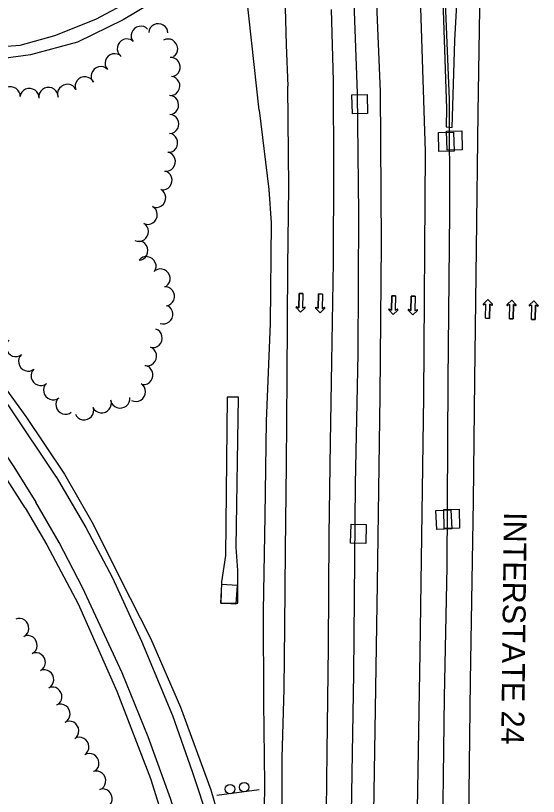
# Model space of a CAD drawing. Extents: x 1746010 to 1754829, y 655801 to 663091.
# Drawn here: x 1753745.9 to 1754020.4, y 656558.2 to 656968.4 of the extents above; entities that cross this region are included whole.
import ezdxf

# ---------------------------------------------------------------- set-up
doc = ezdxf.new("R2010")
doc.units = 0
for name, color, linetype in [('SURVEY - AERIAL SURVEY - Photo Control - Points - Elevations', 7, 'Continuous'), ('SURVEY - AERIAL SURVEY - Photo Control - Points - Locators', 7, 'Continuous'), ('SURVEY - AERIAL SURVEY - Photo Control - Points - Numbers', 7, 'Continuous'), ('SURVEY - AERIAL SURVEY - Photo Control with Text', 7, 'Continuous'), ('SURVEY - CENTERLINE - Existing Roads Text', 7, 'Continuous'), ('SURVEY - CENTERLINE - Preliminary - Development', 7, 'Continuous'), ('SURVEY - CONTROL - Points - Numbers', 7, 'Continuous'), ('SURVEY - DRAINAGE - Area Shapes - Points - Elevations', 7, 'Continuous')]:
    doc.layers.add(name, color=color, linetype=linetype)

msp = doc.modelspace()

# ---------------------------------------------------------------- linework, layer by layer
at = {"layer": 'SURVEY - AERIAL SURVEY - Photo Control - Points - Elevations'}
msp.add_lwpolyline([(1753857, 656767.99), (1753856.02, 656684.7), (1753853.97, 656670.89), (1753853.69, 656659.8), (1753862.61, 656659.78), (1753862.57, 656676.91), (1753861.67, 656689.16), (1753862.86, 656768.04), (1753857, 656767.99)], dxfattribs=at)
at = {"layer": 'SURVEY - AERIAL SURVEY - Photo Control - Points - Locators'}
for points in [[(1753750.9, 656709.87), (1753724.61, 656750.6), (1753704.23, 656778), (1753683.06, 656805.93), (1753655.94, 656838.53), (1753609.06, 656894.35), (1753560.09, 656951.56), (1753528.4, 656989.82), (1753505.99, 657020.44), (1753481.56, 657055.42), (1753460.95, 657096.18), (1753444.01, 657134.51), (1753427.57, 657178.16), (1753416.96, 657225.51), (1753408.73, 657266.76), (1753402.63, 657320.94), (1753400.61, 657379.59), (1753400.54, 657432.05), (1753399.41, 657468.62), (1753398.28, 657476.21)], [(1753403.75, 657476.1), (1753404.01, 657474.57), (1753405.2, 657457.5), (1753406.48, 657401.1), (1753409.51, 657341.24), (1753411.13, 657298.98), (1753413.05, 657276.64), (1753417.91, 657251.78), (1753427.36, 657204.55), (1753437.72, 657170.32), (1753449.26, 657138.75), (1753473.91, 657083.79), (1753493.41, 657050.04), (1753514.93, 657018.21), (1753543.67, 656981.05), (1753569.98, 656950.08), (1753593.84, 656921.5), (1753635.62, 656871.89), (1753673.8, 656825.81), (1753692.62, 656804.39), (1753707.43, 656785.04), (1753725.46, 656760.68), (1753744.98, 656731.33), (1753756.51, 656712.8)], [(1753767.31, 656725.98), (1753742.66, 656762.94), (1753722.84, 656789.81), (1753697.42, 656821.53), (1753664.77, 656860.89), (1753628.33, 656904.67), (1753587.35, 656953.18), (1753554.25, 656993.6), (1753530.02, 657024.53), (1753510.82, 657053.49), (1753492.62, 657084.85), (1753475.79, 657118.57), (1753459.38, 657156.41), (1753445.67, 657196.3), (1753437.31, 657229.21), (1753429.3, 657272.81), (1753425.21, 657322.07), (1753423.6, 657371.6), (1753421.91, 657422.15), (1753420.94, 657468), (1753419.62, 657475.78)], [(1753423.3, 657475.71), (1753424.3, 657466.91), (1753426.17, 657420.04), (1753427.09, 657355.71), (1753429.38, 657313.47), (1753432.96, 657276.04), (1753438.61, 657242.9), (1753446.99, 657205.31), (1753459.75, 657165.22), (1753475.12, 657126.8), (1753497.06, 657082.9), (1753524.77, 657037.47), (1753551.83, 657000.76), (1753586.14, 656960.76), (1753635.92, 656900.77), (1753699.64, 656825.91), (1753726.34, 656792.07), (1753751.29, 656757.89), (1753771.59, 656727.52)], [(1753965.29, 657045.03), (1753969.78, 656986.81), (1753972.15, 656919.55), (1753972.04, 656909.9), (1753975.16, 656909.61), (1753976.56, 656955.34), (1753980.46, 657028.6), (1753982.03, 657067.54)], [(1753991.68, 657069.51), (1753989.79, 656994.07), (1753988.51, 656917.34), (1753987.63, 656845.93), (1753986.9, 656777.13), (1753986.19, 656713.33), (1753984.5, 656618.92), (1753983.53, 656530.59), (1753982.02, 656453.23), (1753981.29, 656391.76), (1753979.87, 656290.99), (1753978.52, 656188.25), (1753977.29, 656086), (1753975.64, 655980.75), (1753974.7, 655894.53), (1753973.26, 655807.54)], [(1753945.21, 655807.54), (1753945.71, 655839.43), (1753947.46, 655954.84), (1753949.86, 656090.09), (1753951.64, 656208.18), (1753953.96, 656365.1), (1753956.15, 656510.33), (1753958.33, 656633.76), (1753960.21, 656768.19), (1753961.13, 656897.07), (1753957.75, 656999.64), (1753954.79, 657040.59)], [(1753934.34, 656999.68), (1753937.35, 656928.49), (1753937.83, 656848.86), (1753937.15, 656768.64), (1753935.67, 656669.84), (1753934.34, 656582.14), (1753932.9, 656495.46), (1753931.11, 656385.87), (1753929.83, 656290.6), (1753928.48, 656204.07), (1753926.32, 656083.91), (1753924.94, 655990.25), (1753923.13, 655865.62), (1753922.15, 655807.78)], [(1753886.83, 656992.14), (1753888.03, 656953.03), (1753888.8, 656931.26)], [(1753631.32, 656977.42), (1753657.14, 656965.74), (1753674.64, 656959.75), (1753692.93, 656955.53), (1753710.33, 656952.86), (1753731.8, 656951.72), (1753748.29, 656952.91), (1753766.54, 656957.92), (1753787.96, 656966.58), (1753807.07, 656976.95)], [(1753873.7, 656918.81), (1753867.13, 656979.71)], [(1753818.01, 656975.55), (1753802.43, 656966.23), (1753778.48, 656954.5), (1753753.72, 656947.84), (1753739.58, 656945.85), (1753716.1, 656946.27), (1753683.43, 656951.62), (1753660.09, 656959.1), (1753635.24, 656970.59)], [(1753911.58, 656971.59), (1753912.64, 656934.08), (1753912.82, 656887.25), (1753912.7, 656839.09), (1753911.76, 656786.44), (1753911.02, 656744.09), (1753910.41, 656695.47), (1753910.01, 656636.87), (1753909.36, 656581.72), (1753908.73, 656535.43), (1753907.55, 656485.64), (1753906.86, 656418.94), (1753906.17, 656369.03), (1753905.58, 656318.08), (1753904.54, 656261.45), (1753903.46, 656192.68), (1753902.26, 656132.87), (1753901.8, 656071.81), (1753900.44, 656014.99), (1753899.79, 655943.06), (1753898.72, 655891.08), (1753897.3, 655813.85), (1753897.22, 655808.04)], [(1753885.79, 656539.28), (1753885.89, 656578.58), (1753886.86, 656614.81), (1753887.19, 656647.39), (1753887.64, 656687.82), (1753888.14, 656732.45), (1753888.46, 656778.56), (1753888.91, 656836.35), (1753889.39, 656878.3), (1753888.8, 656931.26)], [(1753873.7, 656918.81), (1753878.92, 656877.06), (1753880.13, 656859.47), (1753879.47, 656806.65), (1753877.54, 656755.42), (1753876.71, 656705.59), (1753875.89, 656655.77), (1753875.99, 656607.65), (1753876.55, 656564.64), (1753875.84, 656511.45), (1753875.98, 656470.45), (1753871.82, 656470.28), (1753871.62, 656472.92)], [(1753771.59, 656727.52), (1753786.59, 656701.18), (1753800.6, 656673.09), (1753816.65, 656641.34), (1753832.46, 656605.12), (1753848.37, 656561.69), (1753861.15, 656517.6), (1753868.9, 656488.21), (1753871.62, 656472.92)], [(1753767.28, 656726.03), (1753782.76, 656699.45), (1753796.75, 656673.11), (1753812.09, 656639.7), (1753828.24, 656600.74), (1753838.67, 656571.33), (1753847.34, 656544.8)], [(1753862.05, 655808.41), (1753862.57, 655841.24), (1753863.76, 655890.45), (1753864.45, 655928.59), (1753865.28, 655971.66), (1753865.87, 656022.61), (1753866.62, 656070.55), (1753866.95, 656126.69), (1753867.66, 656174.28), (1753867.18, 656212.99), (1753867.01, 656258.07), (1753866.19, 656318.05), (1753864.18, 656364.14), (1753861.71, 656393.35), (1753857.69, 656427.83), (1753851.4, 656465.34), (1753843.74, 656499.88), (1753836.64, 656527.31), (1753827.19, 656557.05), (1753815.52, 656589.59), (1753801.88, 656623.23), (1753781.03, 656667.97), (1753768.76, 656691.65), (1753756.51, 656712.8)], [(1753750.9, 656709.87), (1753762.28, 656690.3), (1753778.72, 656659.45), (1753799, 656613.54), (1753816.81, 656567.71), (1753833.11, 656515.15), (1753844.95, 656465.51), (1753852.21, 656424.47), (1753856.81, 656372.63), (1753859.37, 656308.23), (1753860.01, 656249.15), (1753860.06, 656189.48), (1753860.62, 656140.29), (1753859.78, 656093.37), (1753859.81, 656047.81), (1753859.08, 655997.53), (1753857.72, 655948.06), (1753857.22, 655896.67), (1753857.34, 655846.8), (1753856.24, 655808.47)]]:
    msp.add_lwpolyline(points, dxfattribs=at)
at = {"layer": 'SURVEY - AERIAL SURVEY - Photo Control - Points - Numbers'}
for points in [[(1753959.34, 655807.53), (1753959.92, 655877.58), (1753961.6, 655961.39), (1753962.3, 656049.9), (1753963.82, 656144.04), (1753965.44, 656241.01), (1753966.84, 656337.35), (1753968.08, 656438.44), (1753969.78, 656513.74), (1753971.14, 656610.31), (1753972.49, 656678.9), (1753972.99, 656776.8), (1753973.82, 656865.21), (1753973.77, 656924.3), (1753971.68, 656975.27), (1753968.21, 657018.84), (1753965.85, 657046.35)], [(1753922.72, 656994.79), (1753925.18, 656927.59), (1753925.98, 656864.35), (1753925.56, 656790.71), (1753924.17, 656722.34), (1753923.24, 656622.61), (1753921.81, 656528.59), (1753920.02, 656430.19), (1753918.5, 656325.43), (1753917.39, 656231.6), (1753914.48, 656115.6), (1753913.35, 656013.48), (1753911.14, 655910.91), (1753909.83, 655807.91)]]:
    msp.add_lwpolyline(points, dxfattribs=at)
at = {"layer": 'SURVEY - AERIAL SURVEY - Photo Control with Text'}
msp.add_line((1753873.82, 656561.71), (1753851.63, 656558.62), dxfattribs=at)
for centre in [(1753858.48, 656562.05), (1753865.91, 656563.09)]:
    msp.add_circle(centre, 2.5, dxfattribs=at)
at = {"layer": 'SURVEY - CENTERLINE - Existing Roads Text'}
for centre, major_axis in [((1753811.43, 656958.02), (3.81, 3.24)), ((1753820.83, 656959.42), (5, -0.15)), ((1753804.1, 656951.27), (3.18, 3.86)), ((1753826.22, 656951.19), (2.62, -4.26)), ((1753797.75, 656943.56), (3.67, 3.4)), ((1753827.65, 656941.38), (0.54, -4.97)), ((1753790.42, 656936.77), (3.67, 3.4)), ((1753782.09, 656931.51), (4.6, 1.97)), ((1753827.42, 656931.43), (-0.37, -4.99)), ((1753772.9, 656927.57), (4.6, 1.97)), ((1753743.31, 656926.28), (4.98, -0.44)), ((1753753.27, 656925.4), (4.98, -0.44)), ((1753763.13, 656925.96), (4.94, 0.79)), ((1753826.81, 656921.46), (0.05, -5)), ((1753826.92, 656911.48), (0.05, -5)), ((1753826.31, 656901.56), (-0.44, -4.98)), ((1753825.1, 656891.68), (-0.88, -4.92)), ((1753823.35, 656881.84), (-0.88, -4.92)), ((1753819.99, 656872.54), (-2.17, -4.5)), ((1753815.53, 656863.61), (-2.32, -4.43)), ((1753810.9, 656854.75), (-2.32, -4.43)), ((1753810.62, 656844.94), (0.18, -5)), ((1753814.82, 656837), (4.02, -2.97)), ((1753822.23, 656830.45), (2.94, -4.04)), ((1753824.59, 656820.99), (0.59, -4.97)), ((1753823.68, 656811.35), (-1.92, -4.62)), ((1753818.14, 656798.95), (-1.47, -4.78)), ((1753745.77, 656794.1), (-3.27, 3.79)), ((1753815.2, 656789.39), (-1.47, -4.78)), ((1753752.3, 656786.52), (-3.27, 3.79)), ((1753813.27, 656779.62), (-0.6, -4.96)), ((1753758.84, 656778.95), (-3.27, 3.79)), ((1753765.37, 656771.38), (-3.27, 3.79)), ((1753809.32, 656770.61), (-2.49, -4.34)), ((1753771.9, 656763.81), (-3.27, 3.79)), ((1753791.24, 656764.46), (-4.63, -1.9)), ((1753800.88, 656766.91), (-4.93, -0.84)), ((1753781.95, 656760.77), (-4.67, -1.79)), ((1753748.12, 656646.81), (2.17, -4.5)), ((1753752.47, 656637.8), (2.17, -4.5)), ((1753756.82, 656628.8), (2.17, -4.5)), ((1753761.16, 656619.8), (2.17, -4.5)), ((1753765.47, 656610.78), (2.14, -4.52)), ((1753769.75, 656601.75), (2.14, -4.52)), ((1753774.33, 656592.88), (2.64, -4.24)), ((1753779.61, 656584.39), (2.64, -4.24)), ((1753784.9, 656575.9), (2.64, -4.24)), ((1753788.49, 656566.59), (1.69, -4.71)), ((1753791.87, 656557.18), (1.69, -4.71))]:
    msp.add_ellipse(centre, major_axis=major_axis, ratio=0.940188, start_param=0, end_param=3.141593, dxfattribs=at)
at = {"layer": 'SURVEY - CENTERLINE - Preliminary - Development'}
for p, q in [((1753926.61, 656921.83), (1753926.61, 656921.83)), ((1753971.97, 656902.12), (1753971.97, 656902.12)), ((1753976.27, 656902.79), (1753976.27, 656902.79)), ((1753970.73, 656703.59), (1753970.73, 656703.59)), ((1753974.85, 656703.98), (1753974.85, 656703.98)), ((1753925.89, 656696.13), (1753925.89, 656696.13)), ((1753857.89, 656664.43), (1753857.89, 656664.43))]:
    msp.add_line(p, q, dxfattribs=at)
for points in [[(1753922.5, 656926.74), (1753930.5, 656926.91), (1753930.72, 656916.92), (1753922.72, 656916.74), (1753922.5, 656926.74)], [(1753972.11, 656907.66), (1753980.11, 656907.9), (1753980.42, 656897.91), (1753972.42, 656897.67), (1753972.11, 656907.66)], [(1753967.85, 656907.02), (1753975.85, 656907.22), (1753976.1, 656897.23), (1753968.1, 656897.03), (1753967.85, 656907.02)], [(1753966.46, 656708.36), (1753974.45, 656708.81), (1753975, 656698.82), (1753967.02, 656698.38), (1753966.46, 656708.36)], [(1753970.74, 656708.9), (1753978.74, 656709.06), (1753978.95, 656699.07), (1753970.95, 656698.9), (1753970.74, 656708.9)], [(1753922.04, 656701.25), (1753930.04, 656701), (1753929.74, 656691.01), (1753921.74, 656691.25), (1753922.04, 656701.25)], [(1753854.2, 656669.67), (1753862.19, 656669.18), (1753861.58, 656659.2), (1753853.59, 656659.68), (1753854.2, 656669.67)]]:
    msp.add_lwpolyline(points, dxfattribs=at)
at = {"layer": 'SURVEY - DRAINAGE - Area Shapes - Points - Elevations'}
for p, q in [((1753894.56, 656814.89), (1753894.74, 656822.41)), ((1753894.74, 656822.41), (1753894.56, 656814.89)), ((1753894.74, 656822.41), (1753896.7, 656822.36)), ((1753896.7, 656822.36), (1753894.74, 656822.41)), ((1753896.7, 656822.36), (1753896.52, 656814.84)), ((1753896.7, 656822.36), (1753896.52, 656814.84)), ((1753904.82, 656814.65), (1753905, 656822.17)), ((1753905, 656822.17), (1753904.82, 656814.65)), ((1753905, 656822.17), (1753906.97, 656822.12)), ((1753906.97, 656822.12), (1753905, 656822.17)), ((1753906.97, 656822.12), (1753906.79, 656814.6)), ((1753906.97, 656822.12), (1753906.79, 656814.6)), ((1753943.2, 656813.74), (1753943.37, 656821.26)), ((1753943.37, 656821.26), (1753943.2, 656813.74)), ((1753943.37, 656821.26), (1753945.34, 656821.21)), ((1753945.34, 656821.21), (1753943.37, 656821.26)), ((1753945.34, 656821.21), (1753945.16, 656813.69)), ((1753945.34, 656821.21), (1753945.16, 656813.69)), ((1753953.46, 656813.5), (1753953.64, 656821.02)), ((1753953.64, 656821.02), (1753953.46, 656813.5)), ((1753953.64, 656821.02), (1753955.6, 656820.97)), ((1753955.6, 656820.97), (1753953.64, 656821.02)), ((1753955.6, 656820.97), (1753955.43, 656813.45)), ((1753955.6, 656820.97), (1753955.43, 656813.45)), ((1753991.42, 656816.87), (1753993.87, 656819.2)), ((1753993.87, 656819.2), (1753991.42, 656816.87)), ((1753993.87, 656819.2), (1753996.2, 656816.75)), ((1753993.87, 656819.2), (1753996.2, 656816.75)), ((1754003.92, 656816.57), (1754006.36, 656818.9)), ((1754006.36, 656818.9), (1754003.92, 656816.57)), ((1754006.36, 656818.9), (1754008.69, 656816.46)), ((1754006.36, 656818.9), (1754008.69, 656816.46)), ((1754015.52, 656816.3), (1754017.97, 656818.63)), ((1754017.97, 656818.63), (1754015.52, 656816.3)), ((1754017.97, 656818.63), (1754020.3, 656816.18)), ((1754017.97, 656818.63), (1754020.3, 656816.18)), ((1753895.49, 656812.55), (1753893.16, 656814.99)), ((1753895.49, 656812.55), (1753893.16, 656814.99)), ((1753893.43, 656815.39), (1753894.56, 656814.89)), ((1753894.56, 656814.89), (1753893.43, 656815.39)), ((1753897.93, 656814.88), (1753895.49, 656812.55)), ((1753895.49, 656812.55), (1753897.93, 656814.88)), ((1753896.52, 656814.84), (1753897.67, 656815.29)), ((1753896.52, 656814.84), (1753897.67, 656815.29)), ((1753905.75, 656812.31), (1753903.42, 656814.75)), ((1753905.75, 656812.31), (1753903.42, 656814.75)), ((1753903.7, 656815.15), (1753904.82, 656814.65)), ((1753904.82, 656814.65), (1753903.7, 656815.15)), ((1753908.19, 656814.64), (1753905.75, 656812.31)), ((1753905.75, 656812.31), (1753908.19, 656814.64)), ((1753906.79, 656814.6), (1753907.93, 656815.05)), ((1753906.79, 656814.6), (1753907.93, 656815.05)), ((1753944.12, 656811.4), (1753941.79, 656813.84)), ((1753944.12, 656811.4), (1753941.79, 656813.84)), ((1753942.07, 656814.24), (1753943.2, 656813.74)), ((1753943.2, 656813.74), (1753942.07, 656814.24)), ((1753946.57, 656813.73), (1753944.12, 656811.4)), ((1753944.12, 656811.4), (1753946.57, 656813.73)), ((1753945.16, 656813.69), (1753946.31, 656814.14)), ((1753945.16, 656813.69), (1753946.31, 656814.14)), ((1753954.39, 656811.16), (1753952.06, 656813.6)), ((1753954.39, 656811.16), (1753952.06, 656813.6)), ((1753952.33, 656813.99), (1753953.46, 656813.5)), ((1753953.46, 656813.5), (1753952.33, 656813.99)), ((1753956.83, 656813.49), (1753954.39, 656811.16)), ((1753954.39, 656811.16), (1753956.83, 656813.49)), ((1753955.43, 656813.45), (1753956.57, 656813.89)), ((1753955.43, 656813.45), (1753956.57, 656813.89)), ((1753992.83, 656816.9), (1753991.68, 656816.46)), ((1753992.83, 656816.9), (1753991.68, 656816.46)), ((1753992.65, 656809.38), (1753992.83, 656816.9)), ((1753992.65, 656809.38), (1753992.83, 656816.9)), ((1753994.8, 656816.86), (1753994.62, 656809.34)), ((1753994.62, 656809.34), (1753994.8, 656816.86)), ((1753995.92, 656816.36), (1753994.8, 656816.86)), ((1753994.8, 656816.86), (1753995.92, 656816.36)), ((1754005.32, 656816.61), (1754004.18, 656816.16)), ((1754005.32, 656816.61), (1754004.18, 656816.16)), ((1754005.15, 656809.09), (1754005.32, 656816.61)), ((1754005.15, 656809.09), (1754005.32, 656816.61)), ((1754007.29, 656816.56), (1754007.11, 656809.04)), ((1754007.11, 656809.04), (1754007.29, 656816.56)), ((1754008.42, 656816.06), (1754007.29, 656816.56)), ((1754007.29, 656816.56), (1754008.42, 656816.06)), ((1754016.93, 656816.33), (1754015.78, 656815.89)), ((1754016.93, 656816.33), (1754015.78, 656815.89)), ((1754016.75, 656808.81), (1754016.93, 656816.33)), ((1754016.75, 656808.81), (1754016.93, 656816.33)), ((1754018.89, 656816.29), (1754018.72, 656808.77)), ((1754018.72, 656808.77), (1754018.89, 656816.29)), ((1754020.02, 656815.79), (1754018.89, 656816.29)), ((1754018.89, 656816.29), (1754020.02, 656815.79)), ((1753994.62, 656809.34), (1753992.65, 656809.38)), ((1753992.65, 656809.38), (1753994.62, 656809.34)), ((1754007.11, 656809.04), (1754005.15, 656809.09)), ((1754005.15, 656809.09), (1754007.11, 656809.04)), ((1754018.72, 656808.77), (1754016.75, 656808.81)), ((1754016.75, 656808.81), (1754018.72, 656808.77))]:
    msp.add_line(p, q, dxfattribs=at)
for centre, start, end in [((1753893.33, 656815.16), 66.1964, 223.6447), ((1753893.33, 656815.16), 66.1964, 223.6447), ((1753897.76, 656815.06), 313.6447, 111.1379), ((1753897.76, 656815.06), 313.6447, 111.1379), ((1753903.6, 656814.92), 66.1964, 223.6447), ((1753903.6, 656814.92), 66.1964, 223.6447), ((1753908.02, 656814.82), 313.6447, 111.1379), ((1753908.02, 656814.82), 313.6447, 111.1379), ((1753941.97, 656814.01), 66.1964, 223.6447), ((1753941.97, 656814.01), 66.1964, 223.6447), ((1753946.4, 656813.91), 313.6447, 111.1379), ((1753946.4, 656813.91), 313.6447, 111.1379), ((1753952.23, 656813.77), 66.1964, 223.6447), ((1753952.23, 656813.77), 66.1964, 223.6447), ((1753956.66, 656813.66), 313.6447, 111.1379), ((1753956.66, 656813.66), 313.6447, 111.1379), ((1753991.59, 656816.69), 133.6447, 291.1379), ((1753991.59, 656816.69), 133.6447, 291.1379), ((1753996.02, 656816.58), 246.1964, 43.6447), ((1753996.02, 656816.58), 246.1964, 43.6447), ((1754004.09, 656816.39), 133.6447, 291.1379), ((1754004.09, 656816.39), 133.6447, 291.1379), ((1754008.52, 656816.29), 246.1964, 43.6447), ((1754008.52, 656816.29), 246.1964, 43.6447), ((1754015.69, 656816.12), 133.6447, 291.1379), ((1754015.69, 656816.12), 133.6447, 291.1379), ((1754020.12, 656816.01), 246.1964, 43.6447), ((1754020.12, 656816.01), 246.1964, 43.6447)]:
    msp.add_arc(centre, 0.246, start, end, dxfattribs=at)

# ---------------------------------------------------------------- texts
at = {"layer": 'SURVEY - CONTROL - Points - Numbers'}
msp.add_text('INTERSTATE 24', height=12, rotation=269.3247, dxfattribs=at).set_placement((1754002.28, 656707.66))

doc.saveas('drawing.dxf')
